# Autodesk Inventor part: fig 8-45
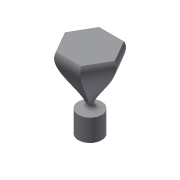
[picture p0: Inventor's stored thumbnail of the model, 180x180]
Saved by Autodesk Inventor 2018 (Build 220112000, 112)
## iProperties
Created: 2004-05
Part Number: fig 8-45
Document SubType Name: Modeling
Designer: CADCIM Technologies
Manufacturer: Standard
Standards Organization: Custom
Density: 1 g/cm^3
Material: Generic
Appearance: Default
Author: CADCIM Technologies
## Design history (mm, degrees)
sketch "Sketch1"
  geometry: C1 r 16.344 at (0, 0)
  constraints: 1 centre point
extrude "Extrusion1" new body sketch "Sketch1" distance "d0" = 30.75; taper "d1" = 0 deg
workplane "Work Plane1"
sketch "Sketch2"
  geometry: L1 (34.788, 0)-(17.394, -30.128); L2 (17.394, -30.128)-(-17.394, -30.128); L3 (-17.394, -30.128)-(-34.788, 0); L4 (-34.788, 0)-(-17.394, 30.128); L5 (-17.394, 30.128)-(17.394, 30.128); L6 (17.394, 30.128)-(34.788, 0); 2 further points
  constraints: 12 end point, 1 coincident, 12 other
loft "Loft2" sketch "Sketch2" dims "d9" = 15, "d10" = 90 deg, "d11" = 80, "d12" = 120 deg
  node "Edges2"
body "Solid1"
other parameters: "d2" = 75
